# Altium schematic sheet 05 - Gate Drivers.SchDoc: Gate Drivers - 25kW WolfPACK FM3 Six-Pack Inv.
size 431 x 279 mm; Date: 07/2023; DocumentNumber: CRD25DA12N-FMC; Revision: 1.1; SheetNumber: 5; SheetTotal: 8; SheetSize: B
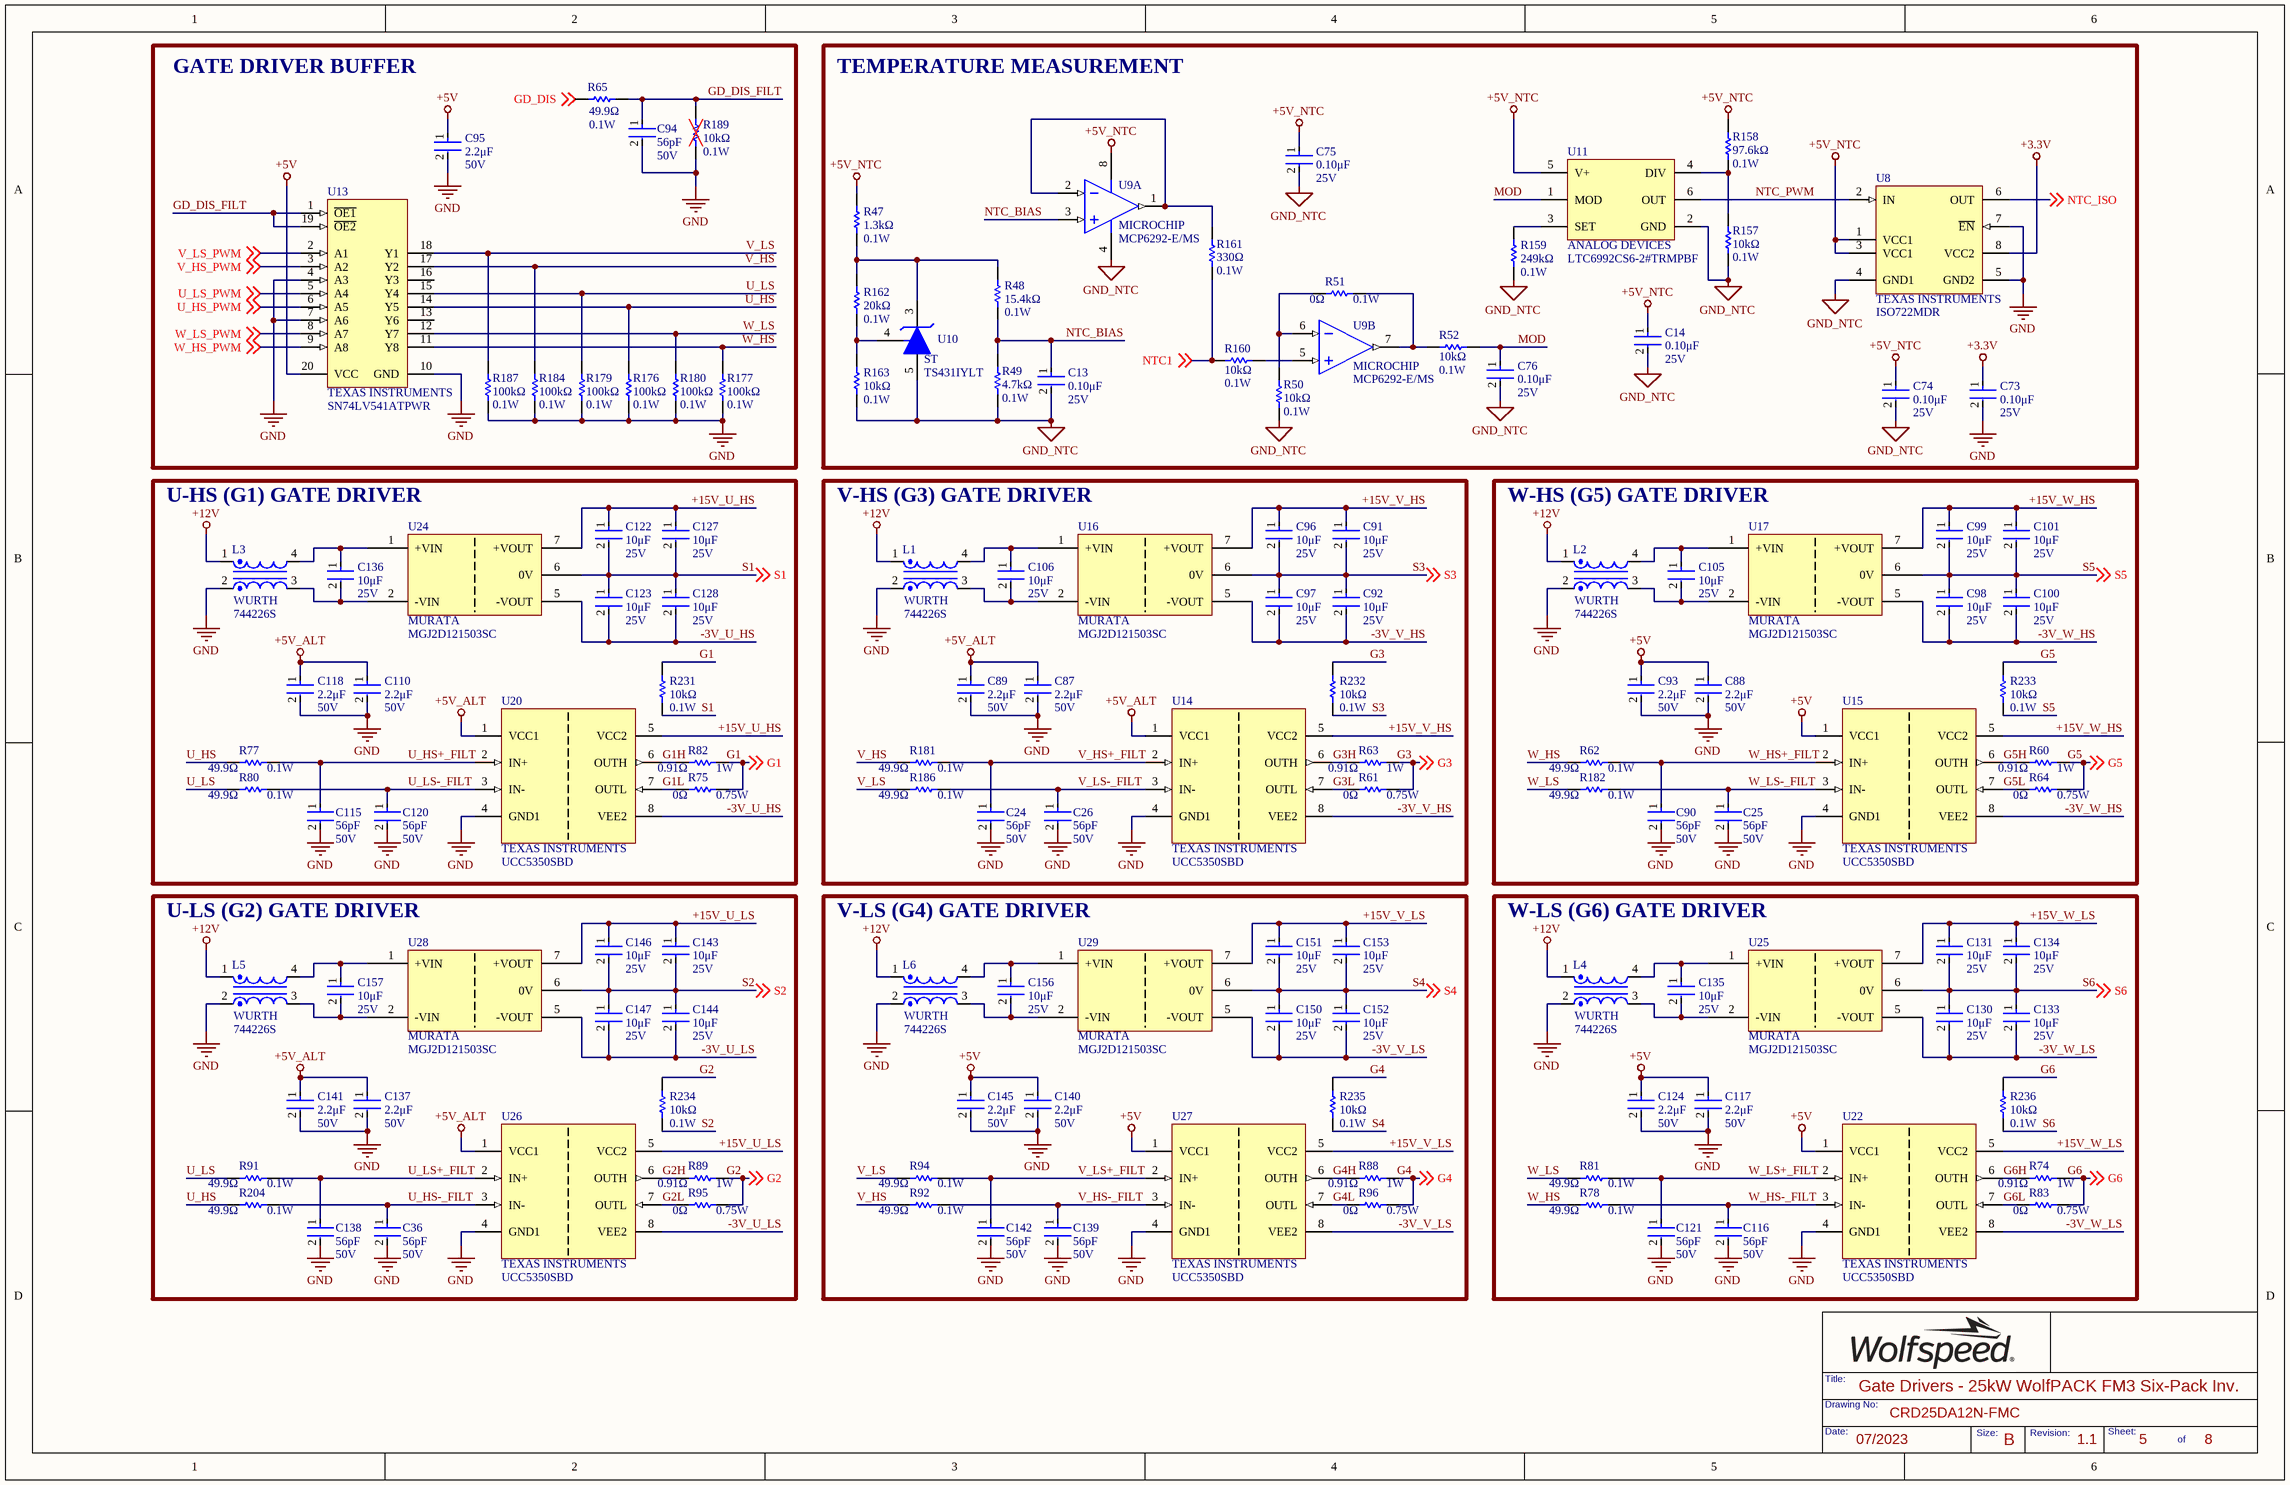
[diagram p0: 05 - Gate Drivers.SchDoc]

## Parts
C13  Voltage Rating: 25V  Capacitance: 0.10μF  [FP-C0603C-CF-IPC_B]  (hidden comment: C0603C104K3RACTU)
C14  Voltage Rating: 25V  Capacitance: 0.10μF  [FP-C0603C-CF-IPC_B]  (hidden comment: C0603C104K3RACTU)
C24  Capacitance: 56pF  Voltage Rating: 50V  [FP-C0603C-CF-IPC_B]  (hidden comment: CL10C560JB8NNNC)
C25  Capacitance: 56pF  Voltage Rating: 50V  [FP-C0603C-CF-IPC_B]  (hidden comment: CL10C560JB8NNNC)
C26  Capacitance: 56pF  Voltage Rating: 50V  [FP-C0603C-CF-IPC_B]  (hidden comment: CL10C560JB8NNNC)
C36  Capacitance: 56pF  Voltage Rating: 50V  [FP-C0603C-CF-IPC_B]  (hidden comment: CL10C560JB8NNNC)
C73  Voltage Rating: 25V  Capacitance: 0.10μF  [FP-C0603C-CF-IPC_B]  (hidden comment: C0603C104K3RACTU)
C74  Voltage Rating: 25V  Capacitance: 0.10μF  [FP-C0603C-CF-IPC_B]  (hidden comment: C0603C104K3RACTU)
C75  Voltage Rating: 25V  Capacitance: 0.10μF  [FP-C0603C-CF-IPC_B]  (hidden comment: C0603C104K3RACTU)
C76  Voltage Rating: 25V  Capacitance: 0.10μF  [FP-C0603C-CF-IPC_B]  (hidden comment: C0603C104K3RACTU)
C87  Voltage Rating: 50V  Capacitance: 2.2μF  [FP-C0603C-CF-IPC_B]  (hidden comment: GRT188R61H225ME13D)
C88  Voltage Rating: 50V  Capacitance: 2.2μF  [FP-C0603C-CF-IPC_B]  (hidden comment: GRT188R61H225ME13D)
C89  Voltage Rating: 50V  Capacitance: 2.2μF  [FP-C0603C-CF-IPC_B]  (hidden comment: GRT188R61H225ME13D)
C90  Capacitance: 56pF  Voltage Rating: 50V  [FP-C0603C-CF-IPC_B]  (hidden comment: CL10C560JB8NNNC)
C91  Voltage Rating: 25V  Capacitance: 10μF  [FP-CL31-IPC_B]  (hidden comment: CL31B106KAHSFNE)
C92  Voltage Rating: 25V  Capacitance: 10μF  [FP-CL31-IPC_B]  (hidden comment: CL31B106KAHSFNE)
C93  Voltage Rating: 50V  Capacitance: 2.2μF  [FP-C0603C-CF-IPC_B]  (hidden comment: GRT188R61H225ME13D)
C94  Capacitance: 56pF  Voltage Rating: 50V  [FP-C0603C-CF-IPC_B]  (hidden comment: CL10C560JB8NNNC)
C95  Voltage Rating: 50V  Capacitance: 2.2μF  [FP-C0603C-CF-IPC_B]  (hidden comment: GRT188R61H225ME13D)
C96  Voltage Rating: 25V  Capacitance: 10μF  [FP-CL31-IPC_B]  (hidden comment: CL31B106KAHSFNE)
C97  Voltage Rating: 25V  Capacitance: 10μF  [FP-CL31-IPC_B]  (hidden comment: CL31B106KAHSFNE)
C98  Voltage Rating: 25V  Capacitance: 10μF  [FP-CL31-IPC_B]  (hidden comment: CL31B106KAHSFNE)
C99  Voltage Rating: 25V  Capacitance: 10μF  [FP-CL31-IPC_B]  (hidden comment: CL31B106KAHSFNE)
C100  Voltage Rating: 25V  Capacitance: 10μF  [FP-CL31-IPC_B]  (hidden comment: CL31B106KAHSFNE)
C101  Voltage Rating: 25V  Capacitance: 10μF  [FP-CL31-IPC_B]  (hidden comment: CL31B106KAHSFNE)
C105  Voltage Rating: 25V  Capacitance: 10μF  [FP-CL31-IPC_B]  (hidden comment: CL31B106KAHSFNE)
C106  Voltage Rating: 25V  Capacitance: 10μF  [FP-CL31-IPC_B]  (hidden comment: CL31B106KAHSFNE)
C110  Voltage Rating: 50V  Capacitance: 2.2μF  [FP-C0603C-CF-IPC_B]  (hidden comment: GRT188R61H225ME13D)
C115  Capacitance: 56pF  Voltage Rating: 50V  [FP-C0603C-CF-IPC_B]  (hidden comment: CL10C560JB8NNNC)
C116  Capacitance: 56pF  Voltage Rating: 50V  [FP-C0603C-CF-IPC_B]  (hidden comment: CL10C560JB8NNNC)
C117  Voltage Rating: 50V  Capacitance: 2.2μF  [FP-C0603C-CF-IPC_B]  (hidden comment: GRT188R61H225ME13D)
C118  Voltage Rating: 50V  Capacitance: 2.2μF  [FP-C0603C-CF-IPC_B]  (hidden comment: GRT188R61H225ME13D)
C120  Capacitance: 56pF  Voltage Rating: 50V  [FP-C0603C-CF-IPC_B]  (hidden comment: CL10C560JB8NNNC)
C121  Capacitance: 56pF  Voltage Rating: 50V  [FP-C0603C-CF-IPC_B]  (hidden comment: CL10C560JB8NNNC)
C122  Voltage Rating: 25V  Capacitance: 10μF  [FP-CL31-IPC_B]  (hidden comment: CL31B106KAHSFNE)
C123  Voltage Rating: 25V  Capacitance: 10μF  [FP-CL31-IPC_B]  (hidden comment: CL31B106KAHSFNE)
C124  Voltage Rating: 50V  Capacitance: 2.2μF  [FP-C0603C-CF-IPC_B]  (hidden comment: GRT188R61H225ME13D)
C127  Voltage Rating: 25V  Capacitance: 10μF  [FP-CL31-IPC_B]  (hidden comment: CL31B106KAHSFNE)
C128  Voltage Rating: 25V  Capacitance: 10μF  [FP-CL31-IPC_B]  (hidden comment: CL31B106KAHSFNE)
C130  Voltage Rating: 25V  Capacitance: 10μF  [FP-CL31-IPC_B]  (hidden comment: CL31B106KAHSFNE)
C131  Voltage Rating: 25V  Capacitance: 10μF  [FP-CL31-IPC_B]  (hidden comment: CL31B106KAHSFNE)
C133  Voltage Rating: 25V  Capacitance: 10μF  [FP-CL31-IPC_B]  (hidden comment: CL31B106KAHSFNE)
C134  Voltage Rating: 25V  Capacitance: 10μF  [FP-CL31-IPC_B]  (hidden comment: CL31B106KAHSFNE)
C135  Voltage Rating: 25V  Capacitance: 10μF  [FP-CL31-IPC_B]  (hidden comment: CL31B106KAHSFNE)
C136  Voltage Rating: 25V  Capacitance: 10μF  [FP-CL31-IPC_B]  (hidden comment: CL31B106KAHSFNE)
C137  Voltage Rating: 50V  Capacitance: 2.2μF  [FP-C0603C-CF-IPC_B]  (hidden comment: GRT188R61H225ME13D)
C138  Capacitance: 56pF  Voltage Rating: 50V  [FP-C0603C-CF-IPC_B]  (hidden comment: CL10C560JB8NNNC)
C139  Capacitance: 56pF  Voltage Rating: 50V  [FP-C0603C-CF-IPC_B]  (hidden comment: CL10C560JB8NNNC)
C140  Voltage Rating: 50V  Capacitance: 2.2μF  [FP-C0603C-CF-IPC_B]  (hidden comment: GRT188R61H225ME13D)
C141  Voltage Rating: 50V  Capacitance: 2.2μF  [FP-C0603C-CF-IPC_B]  (hidden comment: GRT188R61H225ME13D)
C142  Capacitance: 56pF  Voltage Rating: 50V  [FP-C0603C-CF-IPC_B]  (hidden comment: CL10C560JB8NNNC)
C143  Voltage Rating: 25V  Capacitance: 10μF  [FP-CL31-IPC_B]  (hidden comment: CL31B106KAHSFNE)
C144  Voltage Rating: 25V  Capacitance: 10μF  [FP-CL31-IPC_B]  (hidden comment: CL31B106KAHSFNE)
C145  Voltage Rating: 50V  Capacitance: 2.2μF  [FP-C0603C-CF-IPC_B]  (hidden comment: GRT188R61H225ME13D)
C146  Voltage Rating: 25V  Capacitance: 10μF  [FP-CL31-IPC_B]  (hidden comment: CL31B106KAHSFNE)
C147  Voltage Rating: 25V  Capacitance: 10μF  [FP-CL31-IPC_B]  (hidden comment: CL31B106KAHSFNE)
C150  Voltage Rating: 25V  Capacitance: 10μF  [FP-CL31-IPC_B]  (hidden comment: CL31B106KAHSFNE)
C151  Voltage Rating: 25V  Capacitance: 10μF  [FP-CL31-IPC_B]  (hidden comment: CL31B106KAHSFNE)
C152  Voltage Rating: 25V  Capacitance: 10μF  [FP-CL31-IPC_B]  (hidden comment: CL31B106KAHSFNE)
C153  Voltage Rating: 25V  Capacitance: 10μF  [FP-CL31-IPC_B]  (hidden comment: CL31B106KAHSFNE)
C156  Voltage Rating: 25V  Capacitance: 10μF  [FP-CL31-IPC_B]  (hidden comment: CL31B106KAHSFNE)
C157  Voltage Rating: 25V  Capacitance: 10μF  [FP-CL31-IPC_B]  (hidden comment: CL31B106KAHSFNE)
L1  744226S  Manufacturer Print: WURTH  [WE-SL2]
L2  744226S  Manufacturer Print: WURTH  [WE-SL2]
L3  744226S  Manufacturer Print: WURTH  [WE-SL2]
L4  744226S  Manufacturer Print: WURTH  [WE-SL2]
L5  744226S  Manufacturer Print: WURTH  [WE-SL2]
L6  744226S  Manufacturer Print: WURTH  [WE-SL2]
R47  Power Rating: 0.1W  Resistance: 1.3kΩ  [FP-MCR03-IPC_B]  (hidden comment: ERA3AEB132V)
R48  Power Rating: 0.1W  Resistance: 15.4kΩ  [FP-MCR03-IPC_B]  (hidden comment: RC1608F1542CS)
R49  Resistance: 4.7kΩ  Power Rating: 0.1W  [FP-MCR03-IPC_B]  (hidden comment: CRCW06034K70FKTA)
R50  Resistance: 10kΩ  Max Power Dissipation: 0.1W  [FP-MCR03-IPC_B]  (hidden comment: ERJ3EKF1002V)
R51  Resistance: 0Ω  Power Rating: 0.1W  [FP-MCR03-IPC_B]  (hidden comment: CRCW06030000Z0EB)
R52  Resistance: 10kΩ  Max Power Dissipation: 0.1W  [FP-MCR03-IPC_B]  (hidden comment: ERJ3EKF1002V)
R60  value 0.91Ω  Power: 1W  [RESC3125X70X40NL20T20]  (hidden comment: RCWE1210R910FKEA)
R61  value 0Ω  Power Rating: 0.75W  [RESC3125X70X40NL20T20]  (hidden comment: CRCW12100000Z0EAHP)
R62  Resistance: 49.9Ω  Power Rating: 0.1W  [FP-MCR03-IPC_B]  (hidden comment: ERJ-3EKF49R9V)
R63  value 0.91Ω  Power: 1W  [RESC3125X70X40NL20T20]  (hidden comment: RCWE1210R910FKEA)
R64  value 0Ω  Power Rating: 0.75W  [RESC3125X70X40NL20T20]  (hidden comment: CRCW12100000Z0EAHP)
R65  Resistance: 49.9Ω  Power Rating: 0.1W  [FP-MCR03-IPC_B]  (hidden comment: ERJ-3EKF49R9V)
R74  value 0.91Ω  Power: 1W  [RESC3125X70X40NL20T20]  (hidden comment: RCWE1210R910FKEA)
R75  value 0Ω  Power Rating: 0.75W  [RESC3125X70X40NL20T20]  (hidden comment: CRCW12100000Z0EAHP)
R77  Resistance: 49.9Ω  Power Rating: 0.1W  [FP-MCR03-IPC_B]  (hidden comment: ERJ-3EKF49R9V)
R78  Resistance: 49.9Ω  Power Rating: 0.1W  [FP-MCR03-IPC_B]  (hidden comment: ERJ-3EKF49R9V)
R80  Resistance: 49.9Ω  Power Rating: 0.1W  [FP-MCR03-IPC_B]  (hidden comment: ERJ-3EKF49R9V)
R81  Resistance: 49.9Ω  Power Rating: 0.1W  [FP-MCR03-IPC_B]  (hidden comment: ERJ-3EKF49R9V)
R82  value 0.91Ω  Power: 1W  [RESC3125X70X40NL20T20]  (hidden comment: RCWE1210R910FKEA)
R83  value 0Ω  Power Rating: 0.75W  [RESC3125X70X40NL20T20]  (hidden comment: CRCW12100000Z0EAHP)
R88  value 0.91Ω  Power: 1W  [RESC3125X70X40NL20T20]  (hidden comment: RCWE1210R910FKEA)
R89  value 0.91Ω  Power: 1W  [RESC3125X70X40NL20T20]  (hidden comment: RCWE1210R910FKEA)
R91  Resistance: 49.9Ω  Power Rating: 0.1W  [FP-MCR03-IPC_B]  (hidden comment: ERJ-3EKF49R9V)
R92  Resistance: 49.9Ω  Power Rating: 0.1W  [FP-MCR03-IPC_B]  (hidden comment: ERJ-3EKF49R9V)
R94  Resistance: 49.9Ω  Power Rating: 0.1W  [FP-MCR03-IPC_B]  (hidden comment: ERJ-3EKF49R9V)
R95  value 0Ω  Power Rating: 0.75W  [RESC3125X70X40NL20T20]  (hidden comment: CRCW12100000Z0EAHP)
R96  value 0Ω  Power Rating: 0.75W  [RESC3125X70X40NL20T20]  (hidden comment: CRCW12100000Z0EAHP)
R157  Resistance: 10kΩ  Max Power Dissipation: 0.1W  [FP-MCR03-IPC_B]  (hidden comment: ERJ3EKF1002V)
R158  Resistance: 97.6kΩ  Max Power Dissipation: 0.1W  [FP-MCR03-IPC_B]  (hidden comment: ERJ-3EKF9762V)
R159  Max Power Dissipation: 0.1W  Resistance: 249kΩ  [FP-MCR03-IPC_B]  (hidden comment: RMCF0603FT249K)
R160  Resistance: 10kΩ  Max Power Dissipation: 0.1W  [FP-MCR03-IPC_B]  (hidden comment: ERJ3EKF1002V)
R161  Resistance: 330Ω  Power Rating: 0.1W  [FP-MCR03-IPC_B]  (hidden comment: RC0603FR-13330RL)
R162  Resistance: 20kΩ  Power Rating: 0.1W  [FP-MCR03-IPC_B]  (hidden comment: CRCW060320K0FKTA)
R163  Resistance: 10kΩ  Max Power Dissipation: 0.1W  [FP-MCR03-IPC_B]  (hidden comment: ERJ3EKF1002V)
R176  Resistance: 100kΩ  Power Rating: 0.1W  [FP-MCR03-IPC_B]  (hidden comment: RC0603FR-07100KL)
R177  Resistance: 100kΩ  Power Rating: 0.1W  [FP-MCR03-IPC_B]  (hidden comment: RC0603FR-07100KL)
R179  Resistance: 100kΩ  Power Rating: 0.1W  [FP-MCR03-IPC_B]  (hidden comment: RC0603FR-07100KL)
R180  Resistance: 100kΩ  Power Rating: 0.1W  [FP-MCR03-IPC_B]  (hidden comment: RC0603FR-07100KL)
R181  Resistance: 49.9Ω  Power Rating: 0.1W  [FP-MCR03-IPC_B]  (hidden comment: ERJ-3EKF49R9V)
R182  Resistance: 49.9Ω  Power Rating: 0.1W  [FP-MCR03-IPC_B]  (hidden comment: ERJ-3EKF49R9V)
R184  Resistance: 100kΩ  Power Rating: 0.1W  [FP-MCR03-IPC_B]  (hidden comment: RC0603FR-07100KL)
R186  Resistance: 49.9Ω  Power Rating: 0.1W  [FP-MCR03-IPC_B]  (hidden comment: ERJ-3EKF49R9V)
R187  Resistance: 100kΩ  Power Rating: 0.1W  [FP-MCR03-IPC_B]  (hidden comment: RC0603FR-07100KL)
R189  Resistance: 10kΩ  Max Power Dissipation: 0.1W  [FP-MCR03-IPC_B]  (hidden comment: ERJ3EKF1002V)
R204  Resistance: 49.9Ω  Power Rating: 0.1W  [FP-MCR03-IPC_B]  (hidden comment: ERJ-3EKF49R9V)
R231  Resistance: 10kΩ  Max Power Dissipation: 0.1W  [FP-MCR03-IPC_B]  (hidden comment: ERJ3EKF1002V)
R232  Resistance: 10kΩ  Max Power Dissipation: 0.1W  [FP-MCR03-IPC_B]  (hidden comment: ERJ3EKF1002V)
R233  Resistance: 10kΩ  Max Power Dissipation: 0.1W  [FP-MCR03-IPC_B]  (hidden comment: ERJ3EKF1002V)
R234  Resistance: 10kΩ  Max Power Dissipation: 0.1W  [FP-MCR03-IPC_B]  (hidden comment: ERJ3EKF1002V)
R235  Resistance: 10kΩ  Max Power Dissipation: 0.1W  [FP-MCR03-IPC_B]  (hidden comment: ERJ3EKF1002V)
R236  Resistance: 10kΩ  Max Power Dissipation: 0.1W  [FP-MCR03-IPC_B]  (hidden comment: ERJ3EKF1002V)
U8  Manufacturer: TEXAS INSTRUMENTS  [D0008B_L]  (hidden comment: ISO722MDR)
U9  MCP6292-E/MS  Manufacturer Print: MICROCHIP  [MSOP-MS8_L]  (parts A,B of 2)
U10  TS431IYLT  Manufacturer Print: ST  [SOT95P280X145-5N]
U11  LTC6992CS6-2#TRMPBF  MANUFACTURER PRINT: ANALOG DEVICES  [SOT95P280X100-6N]
U13  Manufacturer: TEXAS INSTRUMENTS  [PW0020A_L]  (hidden comment: SN74LV541ATPWR)
U14  UCC5350SBD  Manufacturer Print: TEXAS INSTRUMENTS  [D0008B_HV]
U15  UCC5350SBD  Manufacturer Print: TEXAS INSTRUMENTS  [D0008B_HV]
U16  MGJ2D121503SC  Manufacturer Print: MURATA  [MGJ2D121509SC]
U17  MGJ2D121503SC  Manufacturer Print: MURATA  [MGJ2D121509SC]
U20  UCC5350SBD  Manufacturer Print: TEXAS INSTRUMENTS  [D0008B_HV]
U22  UCC5350SBD  Manufacturer Print: TEXAS INSTRUMENTS  [D0008B_HV]
U24  MGJ2D121503SC  Manufacturer Print: MURATA  [MGJ2D121509SC]
U25  MGJ2D121503SC  Manufacturer Print: MURATA  [MGJ2D121509SC]
U26  UCC5350SBD  Manufacturer Print: TEXAS INSTRUMENTS  [D0008B_HV]
U27  UCC5350SBD  Manufacturer Print: TEXAS INSTRUMENTS  [D0008B_HV]
U28  MGJ2D121503SC  Manufacturer Print: MURATA  [MGJ2D121509SC]
U29  MGJ2D121503SC  Manufacturer Print: MURATA  [MGJ2D121509SC]

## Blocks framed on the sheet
GATE DRIVER BUFFER: C94 C95 R65 R176 R177 R179 R180 R184 R187 R189 U13
TEMPERATURE MEASUREMENT: C13 C14 C73-C76 R47-R52 R157-R163 U8-U11
U-HS (G1) GATE DRIVER: C110 C115 C118 C120 C122 C123 C127 C128 C136 L3 R75 R77 R80 R82 R231 U20 U24
V-HS (G3) GATE DRIVER: C24 C26 C87 C89 C91 C92 C96 C97 C106 L1 R61 R63 R181 R186 R232 U14 U16
W-HS (G5) GATE DRIVER: C25 C88 C90 C93 C98-C101 C105 L2 R60 R62 R64 R182 R233 U15 U17
U-LS (G2) GATE DRIVER: C36 C137 C138 C141 C143 C144 C146 C147 C157 L5 R89 R91 R95 R204 R234 U26 U28
V-LS (G4) GATE DRIVER: C139 C140 C142 C145 C150-C153 C156 L6 R88 R92 R94 R96 R235 U27 U29
W-LS (G6) GATE DRIVER: C116 C117 C121 C124 C130 C131 C133-C135 L4 R74 R78 R81 R83 R236 U22 U25

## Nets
+3.3V: C73.1 U8.8(VCC2)
+5V: C88.1 C93.1 C95.1 C117.1 C124.1 C140.1 C145.1 U13.20(VCC) U15.1(VCC1) U22.1(VCC1) U27.1(VCC1)
+5V_ALT: C87.1 C89.1 C110.1 C118.1 C137.1 C141.1 U14.1(VCC1) U20.1(VCC1) U26.1(VCC1)
+5V_NTC: C14.1 C74.1 C75.1 R47.2 R158.2 U8.1(VCC1) U8.3(VCC1) U9.8(VDD) U11.5(V+)
+12V: L1.1 L2.1 L3.1 L4.1 L5.1 L6.1
GND: C24.2 C25.2 C26.2 C36.2 C73.2 C87.2 C88.2 C89.2 C90.2 C93.2 C94.2 C95.2 C110.2 C115.2 C116.2 C117.2 C118.2 C120.2 C121.2 C124.2 C137.2 C138.2 C139.2 C140.2 C141.2 C142.2 C145.2 L1.2 L2.2 L3.2 L4.2 L5.2 L6.2 R176.1 R177.1 R179.1 R180.1 R184.1 R187.1 R189.1 U8.5(GND2) U8.7(~{EN}) U13.4(A3) U13.7(A6) U13.10(GND) U14.4(GND1) U15.4(GND1) U20.4(GND1) U22.4(GND1) U26.4(GND1) U27.4(GND1)
GND_NTC: C13.2 C14.2 C74.2 C75.2 C76.2 R49.1 R50.1 R157.1 R159.1 R163.1 U8.4(GND1) U9.4(VSS) U10.5 U11.2(GND)
+15V_U_HS: C122.1 C127.1 U20.5(VCC2) U24.7(+VOUT)
+15V_U_LS: C143.1 C146.1 U26.5(VCC2) U28.7(+VOUT)
+15V_V_HS: C91.1 C96.1 U14.5(VCC2) U16.7(+VOUT)
+15V_V_LS: C151.1 C153.1 U27.5(VCC2) U29.7(+VOUT)
+15V_W_HS: C99.1 C101.1 U15.5(VCC2) U17.7(+VOUT)
+15V_W_LS: C131.1 C134.1 U22.5(VCC2) U25.7(+VOUT)
-3V_U_HS: C123.2 C128.2 U20.8(VEE2) U24.5(-VOUT)
-3V_U_LS: C144.2 C147.2 U26.8(VEE2) U28.5(-VOUT)
-3V_V_HS: C92.2 C97.2 U14.8(VEE2) U16.5(-VOUT)
-3V_V_LS: C150.2 C152.2 U27.8(VEE2) U29.5(-VOUT)
-3V_W_HS: C98.2 C100.2 U15.8(VEE2) U17.5(-VOUT)
-3V_W_LS: C130.2 C133.2 U22.8(VEE2) U25.5(-VOUT)
G1: R75.2 R82.2 R231.2 ; off-sheet G1
G1H: R82.1 U20.6(OUTH)
G1L: R75.1 U20.7(OUTL)
G2: R89.2 R95.2 R234.2 ; off-sheet G2
G2H: R89.1 U26.6(OUTH)
G2L: R95.1 U26.7(OUTL)
G3: R61.2 R63.2 R232.2 ; off-sheet G3
G3H: R63.1 U14.6(OUTH)
G3L: R61.1 U14.7(OUTL)
G4: R88.2 R96.2 R235.2 ; off-sheet G4
G4H: R88.1 U27.6(OUTH)
G4L: R96.1 U27.7(OUTL)
G5: R60.2 R64.2 R233.2 ; off-sheet G5
G5H: R60.1 U15.6(OUTH)
G5L: R64.1 U15.7(OUTL)
G6: R74.2 R83.2 R236.2 ; off-sheet G6
G6H: R74.1 U22.6(OUTH)
G6L: R83.1 U22.7(OUTL)
GD_DIS: R65.1 ; off-sheet GD_DIS
GD_DIS_FILT: C94.1 R65.2 R189.2 U13.1(~{OE1}) U13.19(~{OE2})
MOD: C76.1 R52.1 U11.1(MOD)
NTC1: R160.2 R161.1 ; off-sheet NTC1
NTC_BIAS: C13.1 R48.1 R49.2 U9.3(VINA+)
NTC_ISO: U8.6(OUT) ; off-sheet NTC_ISO
NTC_PWM: U8.2(IN) U11.6(OUT)
S1: C122.2 C123.1 C127.2 C128.1 R231.1 U24.6(0V) ; off-sheet S1
S2: C143.2 C144.1 C146.2 C147.1 R234.1 U28.6(0V) ; off-sheet S2
S3: C91.2 C92.1 C96.2 C97.1 R232.1 U16.6(0V) ; off-sheet S3
S4: C150.1 C151.2 C152.1 C153.2 R235.1 U29.6(0V) ; off-sheet S4
S5: C98.1 C99.2 C100.1 C101.2 R233.1 U17.6(0V) ; off-sheet S5
S6: C130.1 C131.2 C133.1 C134.2 R236.1 U25.6(0V) ; off-sheet S6
U_HS: R77.1 R176.2 R204.1 U13.14(Y5)
U_HS+_FILT: C115.1 R77.2 U20.2(IN+)
U_HS-_FILT: C36.1 R204.2 U26.3(IN-)
U_HS_PWM: U13.6(A5) ; off-sheet U_HS_PWM
U_LS: R80.1 R91.1 R179.2 U13.15(Y4)
U_LS+_FILT: C138.1 R91.2 U26.2(IN+)
U_LS-_FILT: C120.1 R80.2 U20.3(IN-)
U_LS_PWM: U13.5(A4) ; off-sheet U_LS_PWM
V_HS: R92.1 R181.1 R184.2 U13.17(Y2)
V_HS+_FILT: C24.1 R181.2 U14.2(IN+)
V_HS-_FILT: C139.1 R92.2 U27.3(IN-)
V_HS_PWM: U13.3(A2) ; off-sheet V_HS_PWM
V_LS: R94.1 R186.1 R187.2 U13.18(Y1)
V_LS+_FILT: C142.1 R94.2 U27.2(IN+)
V_LS-_FILT: C26.1 R186.2 U14.3(IN-)
V_LS_PWM: U13.2(A1) ; off-sheet V_LS_PWM
W_HS: R62.1 R78.1 R177.2 U13.11(Y8)
W_HS+_FILT: C90.1 R62.2 U15.2(IN+)
W_HS-_FILT: C116.1 R78.2 U22.3(IN-)
W_HS_PWM: U13.9(A8) ; off-sheet W_HS_PWM
W_LS: R81.1 R180.2 R182.1 U13.12(Y7)
W_LS+_FILT: C121.1 R81.2 U22.2(IN+)
W_LS-_FILT: C25.1 R182.2 U15.3(IN-)
W_LS_PWM: U13.8(A7) ; off-sheet W_LS_PWM
NetC105_1: C105.1 L2.4 U17.1(+VIN)
NetC105_2: C105.2 L2.3 U17.2(-VIN)
NetC106_1: C106.1 L1.4 U16.1(+VIN)
NetC106_2: C106.2 L1.3 U16.2(-VIN)
NetC135_1: C135.1 L4.4 U25.1(+VIN)
NetC135_2: C135.2 L4.3 U25.2(-VIN)
NetC136_1: C136.1 L3.4 U24.1(+VIN)
NetC136_2: C136.2 L3.3 U24.2(-VIN)
NetC156_1: C156.1 L6.4 U29.1(+VIN)
NetC156_2: C156.2 L6.3 U29.2(-VIN)
NetC157_1: C157.1 L5.4 U28.1(+VIN)
NetC157_2: C157.2 L5.3 U28.2(-VIN)
NetR47_1: R47.1 R48.2 R162.2 U10.3
NetR50_2: R50.2 R51.1 U9.6(VINB-)
NetR51_2: R51.2 R52.2 U9.7(VOUTB)
NetR157_2: R157.2 R158.1 U11.4(DIV)
NetR159_2: R159.2 U11.3(SET)
NetR160_1: R160.1 U9.5(VINB+)
NetR161_2: R161.2 U9.1(VOUTA) U9.2(VINA-)
NetR162_1: R162.1 R163.2 U10.4

Not connected (* = marked no-connect by the designer): U13 13(Y6) 16(Y3)

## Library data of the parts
C13 C14 C73-C76 = CMP-2006-03057-2: CAP CER 0.1UF 25V X7R 0603; Manufacturer: KEMET; Value: 0.10μF; Material: Ceramic; Tolerance: 0.1; Temperature Coefficient: 30ppm/°C; Automotive Grade: Grade 1
C24-C26 C36 C90 C94 C115 C116 C120 C121 C138 C139 C142 = CL10C560JB8NNNC: CAP CER 56PF 50V C0G/NP0 0603; Manufacturer: SAMSUNG; Material: Ceramic; Tolerance: 5%; Dielectric: C0G; Temperature Coefficient: 30ppm/°C
C87-C89 C93 C95 C110 C117 C118 C124 C137 C140 C141 C145 = GRT188R61H225ME13D: CAP CER 2.2UF 50V X5R 0603; Manufacturer: MURATA; Tolerance: 20%; Value: 2.2μF
C91 C92 C96-C101 C105 C106 C122 C123 C127 C128 C130 C131 C133-C136 C143 C144 C146 C147 C150-C153 C156 C157 = CMP-13271-001434-1: CAP CER 10UF 25V X7R 1206; Manufacturer: SAMSUNG; Tolerance: 10%; Value: 10μF
L1-L6 = 744226S: CMC 10UH 1.6A 2LN 920 OHM SMD; Manufacturer: WURTH ELECTRONIK; Tolerance: 30%; Voltage Rating: 80V; Resistance: 80mR; Impedance: 920R; Number of Lines: 2; Test Frequency: 1kHz; Value: 10μH
R47 = ERA3AEB132V: RES SMD 1.3K OHM 0.1% 1/10W 0603; Manufacturer: PANASONIC; Manufacturer Part Number: ERA-3AEB132V; Temperature Coefficient: 25ppm/°C; Voltage Rating: 75V; Max Power Dissipation: 100mW; Value: 1.3kΩ
R48 = RC1608F1542CS: RES SMD 15.4K OHM 1% 1/10W 0603; Manufacturer: SAMSUNG; Max Power Dissipation: 100mW; Temperature Coefficient: 100ppm/°C; Voltage Rating (DC): 50V; Value: 15.4kΩ
R49 = CRCW06034K70FKTA: RES SMD 4.7K OHM 1% 1/10W 0603; Manufacturer: VISHAY DALE; Voltage Rating: 75V; Max Power Dissipation: 100mW; Temperature Coefficient: 100ppm/°C; Value: 4.7kΩ
R50 R52 R157 R160 R163 R189 R231-R236 = ERJ3EKF1002V: RES SMD 10K OHM 1% 1/10W 0603; Manufacturer: PANASONIC; Manufacturer Part Number: ERJ-3EKF1002V; Temperature Coefficient: 100ppm/°C; Power Rating: 100mW; Voltage Rating: 75V; Value: 10kΩ
R51 = CRCW06030000Z0EB: RES SMD 0 OHM JUMPER 1/10W 0603; Manufacturer: VISHAY DALE; Manufacturer Part Number: CRCW06030000Z0EBC; Max Power Dissipation: 100mW; Voltage Rating: 75V; Tolerance: 1%; Temperature Coefficient: 100ppm/°C; Value: 0Ω
R60 R63 R74 R82 R88 R89 = CMP-2005-02198-1: RES 0.91 OHM 1% 1W 1210; Manufacturer: VISHAY DALE
R61 R64 R75 R83 R95 R96 = CRCW12100000Z0EAHP: RES SMD 0 OHM JUMPER 3/4W 1210; Manufacturer: VISHAY DALE; Max Power Dissipation: 750mW
R62 R65 R77 R78 R80 R81 R91 R92 R94 R181 R182 R186 R204 = ERJ-3EKF49R9V: RES SMD 49.9 OHM 1% 1/10W 0603; Manufacturer: PANASONIC; Temperature Coefficient: 100ppm/°C; Voltage Rating: 75V; Max Power Dissipation: 100mW; Voltage Rating (DC): 50V; Working Voltage: 6V; Value: 49.9Ω
R158 = ERJ-3EKF9762V: RES SMD 97.6K OHM 1% 1/10W 0603; Manufacturer: PANASONIC; Temperature Coefficient: 100ppm/°C; Voltage Rating: 75V; Power Rating: 100mW; Voltage Rating (DC): 50V; Value: 97.6kΩ
R159 = RMCF0603FT249K: RES 249K OHM 1% 1/10W 0603; Manufacturer: STACKPOLE; Temperature Coefficient: 100ppm/°C; Value: 249kΩ
R161 = RC0603FR-13330RL: RES 330 OHM 1% 1/10W 0603; Manufacturer: YAGEO; Voltage Rating: 50V; Temperature Coefficient: 100ppm/°C; Value: 330Ω
R162 = CRCW060320K0FKTA: RES SMD 20K OHM 1% 1/10W 0603; Manufacturer: VISHAY DALE; Temperature Coefficient: 100ppm/°C; Voltage Rating: 75V; Max Power Dissipation: 100mW; Value: 20kΩ
R176 R177 R179 R180 R184 R187 = RC0603FR-07100KL: RES 100K OHM 1% 1/10W 0603; Manufacturer: YAGEO; Temperature Coefficient: 100ppm/°C; Voltage Rating: 50V; Working Voltage: 75V; Max Power Dissipation: 100mW; Value: 100kΩ
U8 = CMP-0328-00055-4: DGTL ISO 2500VRMS 1CH GP 8SOIC; TTL/CMOS Input Threshold: CMOS; Prop Delay(Max)(ns): 16; Input Noise Filter: None; Insulation Rating(VRMS): 2500; Datarate(Mbps): 150; Eco-Plan: Green (RoHS & no Sb/Br); Rating: Catalog; Supply Voltage(s)(V): 3.3, 5; SubFamily: Isolator; Thermal Shutdown: No
U9 = MCP6292-E/MS: IC OPAMP GP 2 CIRCUIT 8MSOP; Number of Channels: 2; Max Supply Voltage: 5.5V; Unity Gain Bandwidth Product: 10MHz; Slew Rate: 7V/µs; Common Mode Rejection Ratio: 70dB; Min Supply Voltage: 2.4V; Voltage Gain: 110dB; Output Current: 25mA; Nominal Supply Current: 1mA; Input Bias Current: 1pA; Input Offset Voltage (Vos): 3mV; Amplifier Type: GENERAL PURPOSE; Input Offset Voltage-Max: 5mV
U10 = TS431IYLT: IC VREF SHUNT ADJ 2% SOT23-5; Manufacturer: STMICROELECTRONICS; Output Voltage: 6V; Max Input Voltage: 10V; Max Output Current: 30mA; Reference Type: Shunt,Adjustable; Number of Channels: 1; Temperature Coefficient: 100ppm/°C; Cathode Current: 60uA; Output Type: Adjustable; Min Output Voltage: 1.24V
U11 = LTC6992CS6-2#TRMPBF: IC OSC SILICON PROG TSOT23-6; Frequency: 3.81Hz; Min Supply Voltage: 2.25V; Max Supply Voltage: 5.5V; Number of Timers/Counters: 1; Operating Supply Current: 365uA
U13 = CMP-0440-01163-3: IC BUF NON-INVERT 5.5V 20TSSOP; Bits(#): 8; Voltage(Nom)(V): 5; ICC @ Nom Voltage(Max)(mA): 0.02; VCC(Max)(V): 5.5; Output Type: CMOS; Rating: Catalog; Input Type: TTL; VCC(Min)(V): 4.5; F @ Nom Voltage(Max)(Mhz): 110; tpd @ Nom Voltage(Max)(ns): 7.9
U14 U15 U20 U22 U26 U27 = UCC5350SBD: 5A/5A, 3-KVRMS SINGLE-CHANNEL IS; Class: U; Working Voltage: 990V; Number of Channels: 1
U16 U17 U24 U25 U28 U29 = MGJ2D121503SC: DC DC CONVERTER 15V -3V 1.7W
